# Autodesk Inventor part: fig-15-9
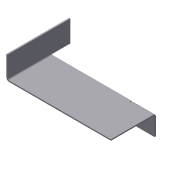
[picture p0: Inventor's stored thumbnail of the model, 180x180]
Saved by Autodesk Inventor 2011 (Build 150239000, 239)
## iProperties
Shininess: 77.0
Angle Display Precision: 2
Document Length Units: 11269
Document Angle Units: 11279
Document Time Units: 11290
Document Mass Units: 11283
Document Length Units Precision: 3
Document Angle Units Precision: 2
Created: 2002-04
Part Number: fig-15-9
Material: Aluminum-6061
Document SubType Name: Sheet Metal
Density: 1 g/cm^3
Sheet Metal Rule: Default
Density: 0.0
Volumn: 0.0
Area: 0.0
PropertySet Name: Model Information
Control State: 0
Master: False
Checked Out: False
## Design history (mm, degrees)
node "Face1"
  sketch "Sketch1"
    geometry: L1 (-49.559, 19.574)-(-49.559, -30.426); L2 (-49.559, -30.426)-(50.441, -30.426); L3 (50.441, -30.426)-(50.441, 19.574); L4 (50.441, 19.574)-(32.941, 19.574); L5 (32.941, 19.574)-(32.941, 4.574); L6 (32.941, 4.574)-(-32.059, 4.574); L7 (-32.059, 4.574)-(-32.059, 19.574); L8 (-32.059, 19.574)-(-49.559, 19.574)
    constraints: 16 end point, 6 parallel, 2 equal length, 1 perpendicular, 1 vertical
    dimensions: "d0" = 100 distance of L1.end L2.end; "d1" = 65 distance of L5.end L6.end; "d2" = 15 distance of L6.end L7.end; "d3" = 50 distance of L1.start L1.end
sketch "Sketch2"
  geometry: L1 (100, 0)-(0, 0) reference; L2 (17.5, 50)-(17.5, 35) reference; L3 (82.5, 50)-(82.5, 0)
  constraints: 2 end point, 1 parallel, 1 point on line
sketch "Sketch3"
  geometry: L1 (81.369, -50)-(0, -50) reference; L2 (17.5, 0)-(17.5, -50)
  constraints: 2 end point, 1 perpendicular, 1 point on line
feature "Fold2" sketch "Sketch3" dims "d8" = 1 (= BendRadius), "d9" = 90 deg, "d10" = 1 (= BendRadius), "d14" = 1 (= BendReliefWidth), "d15" = 0.5 (= BendReliefDepth), "d16" = 2 (= MinimumRemnant), "SeamGap" = 0.01, "Thickness" = 1
sketch "Sketch4"
  geometry: L1 (17.5, 0)-(17.5, -50) reference; L2 (-63.869, -15)-(0, -15) reference; L3 (0, -15)-(17.5, -15)
  constraints: 2 end point, 1 collinear, 1 point on line
feature "Fold3" sketch "Sketch4" dims "d11" = 1 (= BendRadius), "d12" = 90 deg, "d13" = 1 (= BendRadius), "d17" = 1 (= BendReliefWidth), "d18" = 0.5 (= BendReliefDepth), "d19" = 2 (= MinimumRemnant), "SeamGap" = 0.01, "Thickness" = 1
body "Solid1"
face "Plate1" dims "Thickness" = 1
other parameters: "BendRadius" = 1 (= Thickness), "BendReliefWidth" = 1 (= Thickness), "BendReliefDepth" = 0.5 (= 0.5 x Thickness), "CornerReliefSize" = 4 (= 4 x Thickness), "MinimumRemnant" = 2 (= 2 x Thickness), "TransitionRadius" = 1 (= BendRadius), "d4" = 1 (= BendRadius), "JacobiRadiusSize" = 1 (= Thickness), "GapSize" = 1 (= Thickness)
